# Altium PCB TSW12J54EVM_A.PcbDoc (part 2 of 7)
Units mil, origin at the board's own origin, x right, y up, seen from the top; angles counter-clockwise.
Board outline 6301 x 2680 mil, 10 copper layers (Top Layer - L1, Gnd-Plane - L2, Signals - L3, Gnd-Plane - L4, Pwr Plane - L5, Signals - L6, Gnd-Plane - L7, Signals - L8, Gnd-Plane - L9, Bottom Layer - L10), stack 57.8 mil thick; 650 components, 374 nets, 2074 pads, 1402 vias.
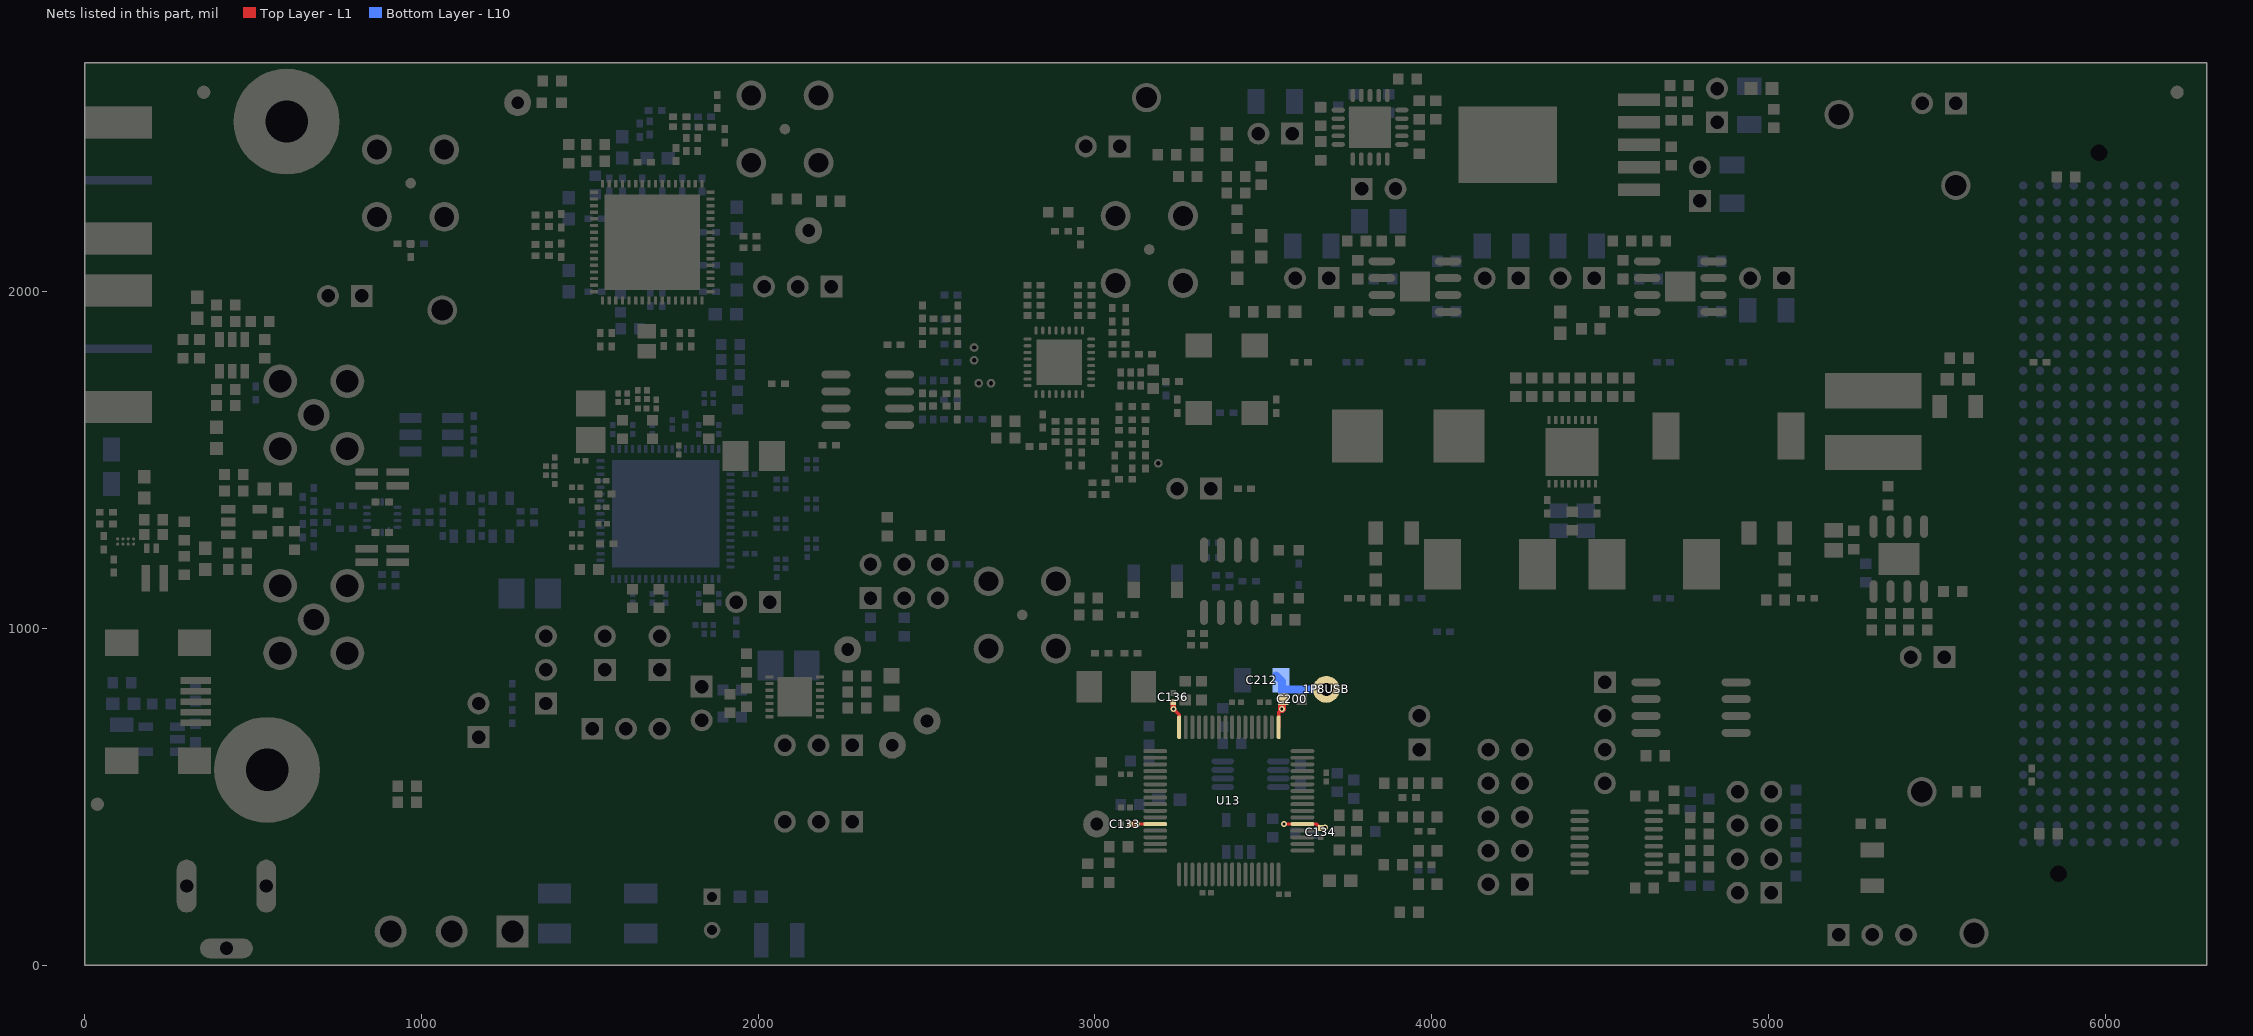
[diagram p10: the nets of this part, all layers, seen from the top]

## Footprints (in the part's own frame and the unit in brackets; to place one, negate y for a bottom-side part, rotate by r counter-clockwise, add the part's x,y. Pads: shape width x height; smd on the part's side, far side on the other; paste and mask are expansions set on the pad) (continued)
0201#2 [mm] "Data from Kemet datasheet CC101_COM dated 7/28/11"
  rect 0.42x0.46 smd mask+0.048: 1(-0.33,0)
  rect 0.46x0.42 smd mask+0.048: 2(0.33,0)
  body extent -0.31,-0.16 0.31,0.16, height 0.26
0306 [mil] "bxl footprint"
  rect 22x67 smd: 1(-20.5,0) 2(20.5,0)
  body extent -17,-33 17,33, height 24
0402L#1 [mm] "0402 from SM-752 data"
  rect 0.6x0.5 smd: 1(-0.5,0) 2(0.5,0)
  body extent -0.55,-0.3 0.55,0.3, height 0.6
0402L#2 [mm] "0402 from SM-752 data"
  rect 0.6x0.5 smd mask+0.071: 1(-0.5,0) 2(0.5,0)
  body extent -0.55,-0.3 0.55,0.3, height 0.6
0402L#3 [mm] "0402 from SM-752 data"
  rect 0.6x0.5 smd: 1(-0.5,0)
  rect 0.6x0.5 smd mask+0.075: 2(0.5,0)
  body extent -0.55,-0.3 0.55,0.3, height 0.6
0402L#4 [mm] "0402 from SM-752 data"
  rect 0.6x0.5 smd: 1(-0.5,0)
  rect 0.6x0.5 smd mask+0.067: 2(0.5,0)
  body extent -0.55,-0.3 0.55,0.3, height 0.6
0402L#5 [mm] "0402 from SM-752 data"
  rect 0.6x0.5 smd mask+0.067: 1(-0.5,0)
  rect 0.6x0.5 smd: 2(0.5,0)
  body extent -0.55,-0.3 0.55,0.3, height 0.6
0402L#6 [mm] "0402 from SM-752 data"
  rect 0.6x0.5 smd mask+0.074: 1(-0.5,0)
  rect 0.6x0.5 smd: 2(0.5,0)
  body extent -0.55,-0.3 0.55,0.3, height 0.6
0402L#7 [mm] "0402 from SM-752 data"
  rect 0.6x0.5 smd: 1(-0.5,0)
  rect 0.6x0.5 smd mask+0.053: 2(0.5,0)
  body extent -0.55,-0.3 0.55,0.3, height 0.6
0402L#8 [mm] "0402 from SM-752 data"
  rect 0.6x0.5 smd mask+0.071: 1(-0.5,0)
  rect 0.6x0.5 smd: 2(0.5,0)
  body extent -0.55,-0.3 0.55,0.3, height 0.6
0402L#9 [mm] "0402 from SM-752 data"
  rect 0.6x0.5 smd: 1(-0.5,0)
  rect 0.6x0.5 smd mask+0.071: 2(0.5,0)
  body extent -0.55,-0.3 0.55,0.3, height 0.6
0402L#10 [mm] "0402 from SM-752 data"
  rect 0.6x0.5 smd mask+0.066: 1(-0.5,0) 2(0.5,0)
  body extent -0.55,-0.3 0.55,0.3, height 0.6
0402L#11 [mm] "0402 from SM-752 data"
  rect 0.6x0.5 smd mask+0.065: 1(-0.5,0)
  rect 0.6x0.5 smd: 2(0.5,0)
  body extent -0.55,-0.3 0.55,0.3, height 0.6
0603 [mm] "0603 from SM-752 data"
  rect 1x0.95 smd: 1(-0.8,0) 2(0.8,0)
  silkscreen extent -1.52,-0.69 1.52,0.69, body extent -0.87,-0.47 0.87,0.47, height 0.85
0603HC [mm] "SMD, 2-Leads, Body 1.8x1.12mm, Lead Spacing 1.28mm"
  rect 0.64x1.02 smd: 1(-0.64,0) 2(0.64,0)
  silkscreen extent -0.18,-0.7 0.18,0.7, body extent -0.9,-0.56 0.9,0.56, height 1.01
0603L#1 [mm] "0603 from SM-752 data"
  rect 0.8x0.85 smd: 1(-0.7,0) 2(0.7,0)
  silkscreen extent -0.07,-0.33 0.07,0.33, body extent -0.87,-0.47 0.87,0.47, height 0.85
0603L#2 [mm] "0603 from SM-752 data"
  rect 0.8x0.85 smd: 1(-0.7,0)
  rect 0.8x0.85 smd mask+0.053: 2(0.7,0)
  silkscreen extent -0.07,-0.33 0.07,0.33, body extent -0.87,-0.47 0.87,0.47, height 0.85
0603L#3 [mm] "0603 from SM-752 data"
  rect 0.8x0.85 smd: 1(-0.7,0)
  rect 0.8x0.85 smd mask+0.064: 2(0.7,0)
  silkscreen extent -0.07,-0.33 0.07,0.33, body extent -0.87,-0.47 0.87,0.47, height 0.85
751-06_N [mm] "SOIC, 8-Leads, Body 4.9x3.9mm, Pitch 1.27mm, IPC Medium Density"
  oval 2.2x0.6 smd: 1(-2.4,1.905) 2(-2.4,0.635) 3(-2.4,-0.635) 4(-2.4,-1.905) 5(2.4,-1.905) 6(2.4,-0.635) 7(2.4,0.635) 8(2.4,1.905)
  silkscreen extent -2.53,-2.5 0.9,2.88, body extent -1.95,-2.45 1.95,2.45, height 1.75
0805L [mm] "0805 from SM-752 data"
  rect 1.1x1.4 smd: 1(-0.75,0) 2(0.75,0)
  body extent -1.1,-0.72 1.1,0.72, height 1.1
1206 [mm] "1206 from SM-752 data"
  rect 1.3x1.85 smd: 1(-1.45,0) 2(1.45,0)
  silkscreen extent -2.4,-1.21 2.4,1.21, body extent -1.7,-0.9 1.7,0.9, height 1.35
1206L [mm] "1206 from SM-752 data"
  rect 1.1x1.75 smd: 1(-1.35,0) 2(1.35,0)
  silkscreen extent -0.4,-0.78 0.4,0.77, body extent -1.7,-0.9 1.7,0.9, height 1.35
1210L [mm] "1210 from SM-752 data"
  rect 1.1x2.6 smd: 1(-1.35,0) 2(1.35,0)
  silkscreen extent -0.4,-1.2 0.4,1.2, body extent -1.7,-1.35 1.7,1.35, height 1.35
3216-18 [mm] "Medium density IPC, based on Kemet T495 dimensions"
  rect 1.8x1.25 smd: 1(-1.3,0) 2(1.3,0)
  silkscreen extent -2.49,-0.54 -2.49,0.54, body extent -1.7,-0.9 1.7,0.9, height 1.8
3528-21 [mm] "Medium Density IPC, based on SM-782 section 8.4"
  rect 1.95x2.25 smd: 1(-1.375,0) 2(1.375,0)
  silkscreen extent -2.66,-1.5 1.9,1.79, body extent -1.85,-1.5 1.85,1.5, height 2.1
AssemblyNote [mil] "Assembly Note"
AssemblyNoteLabel [mil] "Assembly Note for PCB Labels"
CAPPR250W50D630H1120 [mm] "PANASONIC"
  rect 1.25x1.25 hole 0.75: 1(-1.25,0)
  round 1.25 hole 0.75: 2(1.25,0)
  silkscreen extent -3.4,-3.4 3.4,3.4, body extent -3.37,-3.39 3.4,3.39, height 12.21
CDRH6D28 [mm] "Sumida reommended land pattern"
  rect 2.65x7.3 smd: 1(-2.325,0) 2(2.325,0)
  silkscreen extent -4,-4 4,4, body extent -3.5,-3.5 3.5,3.5, height 3
CONN_2510-6002 [mm] "3M 2500 series TS-0770-L December 15, 2011"
  rect 1.65x1.65 hole 1.016 mask+0: 1(-5.08,-1.27)
  round 1.65 hole 1.016 mask+0: 2(-5.08,1.27) 3(-2.54,-1.27) 4(-2.54,1.27) 5(0,-1.27) 6(0,1.27) 7(2.54,-1.27) 8(2.54,1.27) 9(5.08,-1.27) 10(5.08,1.27)
  silkscreen extent -10.01,-4.17 10.01,4.47, body extent -10.01,-4.11 10.01,4.52, height 9.92
CONN_CUI-PJ-202AH [mm] "Conn_DC Jack"
  oval 1.5x4 hole 1 slot 3.5 at 90 deg: 1(0,0) 2(6,0)
  oval 4x1.5 hole 1 slot 3.5 at 0 deg: 3(3,4.7)
  silkscreen extent -0.7,-4.5 13.7,4.5, body extent -0.7,-4.5 13.7,4.9, height 11.02
CONN_LTI_SASF546-P26-X1 [mm]
  round 0.8 smd: 1(0,0)
  round 2.25 hole 1.5 mask+0.051: 2(-2.54,2.54) 3(-2.54,-2.54) 4(2.54,-2.54) 5(2.54,2.54)
  silkscreen extent -3.4,-3.4 3.4,3.4, body extent -3.17,-3.17 3.17,3.17, height 12.53
CONN_SEARAY_ASP-134488-01 [mm]
  round 0.635 hole 1.27 unplated mask+0.572: 401(27.191,0) 402(-27.191,-3.048)
  round 0.64 smd paste+0.125 mask+0.05: A1(24.716,5.715) A2(23.446,5.715) A3(22.176,5.715) A4(20.906,5.715) A5(19.636,5.715) A6(18.366,5.715) A7(17.096,5.715) A8(15.826,5.715) A9(14.556,5.715) A10(13.286,5.715) A11(12.016,5.715) A12(10.746,5.715) A13(9.476,5.715) A14(8.206,5.715) A15(6.936,5.715) A16(5.666,5.715) A17(4.396,5.715) A18(3.126,5.715) A19(1.856,5.715) A20(0.586,5.715) A21(-0.684,5.715) A22(-1.954,5.715) A23(-3.224,5.715) A24(-4.494,5.715) A25(-5.764,5.715) A26(-7.034,5.715) A27(-8.304,5.715) A28(-9.574,5.715) A29(-10.844,5.715) A30(-12.114,5.715) A31(-13.384,5.715) A32(-14.654,5.715) A33(-15.924,5.715) A34(-17.194,5.715) A35(-18.464,5.715) A36(-19.734,5.715) A37(-21.004,5.715) A38(-22.274,5.715) A39(-23.544,5.715) A40(-24.814,5.715) B1(24.716,4.445) B2(23.446,4.445) B3(22.176,4.445) B4(20.906,4.445) B5(19.636,4.445) B6(18.366,4.445) B7(17.096,4.445) B8(15.826,4.445) B9(14.556,4.445) B10(13.286,4.445) B11(12.016,4.445) B12(10.746,4.445) B13(9.476,4.445) B14(8.206,4.445) B15(6.936,4.445) B16(5.666,4.445) B17(4.396,4.445) B18(3.126,4.445) B19(1.856,4.445) B20(0.586,4.445) B21(-0.684,4.445) B22(-1.954,4.445) B23(-3.224,4.445) B24(-4.494,4.445) B25(-5.764,4.445) B26(-7.034,4.445) B27(-8.304,4.445) B28(-9.574,4.445) B29(-10.844,4.445) B30(-12.114,4.445) B31(-13.384,4.445) B32(-14.654,4.445) B33(-15.924,4.445) B34(-17.194,4.445) B35(-18.464,4.445) B36(-19.734,4.445) B37(-21.004,4.445) B38(-22.274,4.445) B39(-23.544,4.445) B40(-24.814,4.445) C1(24.716,3.175) C2(23.446,3.175) C3(22.176,3.175) C4(20.906,3.175) C5(19.636,3.175) C6(18.366,3.175) C7(17.096,3.175) C8(15.826,3.175) C9(14.556,3.175) C10(13.286,3.175) C11(12.016,3.175) C12(10.746,3.175) C13(9.476,3.175) C14(8.206,3.175) C15(6.936,3.175) C16(5.666,3.175) C17(4.396,3.175) C18(3.126,3.175) C19(1.856,3.175) C20(0.586,3.175) C21(-0.684,3.175) C22(-1.954,3.175) C23(-3.224,3.175) C24(-4.494,3.175) C25(-5.764,3.175) C26(-7.034,3.175) C27(-8.304,3.175) C28(-9.574,3.175) C29(-10.844,3.175) C30(-12.114,3.175) C31(-13.384,3.175) C32(-14.654,3.175) C33(-15.924,3.175) C34(-17.194,3.175) C35(-18.464,3.175) C36(-19.734,3.175) C37(-21.004,3.175) C38(-22.274,3.175) C39(-23.544,3.175) C40(-24.814,3.175) D1(24.716,1.905) D2(23.446,1.905) D3(22.176,1.905) D4(20.906,1.905) D5(19.636,1.905) D6(18.366,1.905) D7(17.096,1.905) D8(15.826,1.905) D9(14.556,1.905) D10(13.286,1.905) D11(12.016,1.905) D12(10.746,1.905) D13(9.476,1.905) D14(8.206,1.905) D15(6.936,1.905) D16(5.666,1.905) D17(4.396,1.905) D18(3.126,1.905) D19(1.856,1.905) D20(0.586,1.905) D21(-0.684,1.905) D22(-1.954,1.905) D23(-3.224,1.905) D24(-4.494,1.905) D25(-5.764,1.905) D26(-7.034,1.905) D27(-8.304,1.905) D28(-9.574,1.905) D29(-10.844,1.905) D30(-12.114,1.905) D31(-13.384,1.905) D32(-14.654,1.905) D33(-15.924,1.905) D34(-17.194,1.905) D35(-18.464,1.905) D36(-19.734,1.905) D37(-21.004,1.905) D38(-22.274,1.905) D39(-23.544,1.905) D40(-24.814,1.905) E1(24.716,0.635) E2(23.446,0.635) E3(22.176,0.635) E4(20.906,0.635) E5(19.636,0.635) E6(18.366,0.635) E7(17.096,0.635) E8(15.826,0.635) E9(14.556,0.635) E10(13.286,0.635) E11(12.016,0.635) E12(10.746,0.635) E13(9.476,0.635) E14(8.206,0.635) E15(6.936,0.635) E16(5.666,0.635) E17(4.396,0.635) E18(3.126,0.635) E19(1.856,0.635) E20(0.586,0.635) E21(-0.684,0.635) E22(-1.954,0.635) E23(-3.224,0.635) E24(-4.494,0.635) E25(-5.764,0.635) E26(-7.034,0.635) E27(-8.304,0.635) E28(-9.574,0.635) E29(-10.844,0.635) E30(-12.114,0.635) E31(-13.384,0.635) E32(-14.654,0.635) E33(-15.924,0.635) E34(-17.194,0.635) E35(-18.464,0.635) E36(-19.734,0.635) E37(-21.004,0.635) E38(-22.274,0.635) E39(-23.544,0.635) E40(-24.814,0.635) F1(24.716,-0.635) F2(23.446,-0.635) F3(22.176,-0.635) F4(20.906,-0.635) F5(19.636,-0.635) F6(18.366,-0.635) F7(17.096,-0.635) F8(15.826,-0.635) F9(14.556,-0.635) F10(13.286,-0.635) F11(12.016,-0.635) F12(10.746,-0.635) F13(9.476,-0.635) F14(8.206,-0.635) F15(6.936,-0.635) F16(5.666,-0.635) F17(4.396,-0.635) F18(3.126,-0.635) F19(1.856,-0.635) F20(0.586,-0.635) F21(-0.684,-0.635) F22(-1.954,-0.635) F23(-3.224,-0.635) F24(-4.494,-0.635) F25(-5.764,-0.635) F26(-7.034,-0.635) F27(-8.304,-0.635) F28(-9.574,-0.635) F29(-10.844,-0.635) F30(-12.114,-0.635) F31(-13.384,-0.635) F32(-14.654,-0.635) F33(-15.924,-0.635) F34(-17.194,-0.635) F35(-18.464,-0.635) F36(-19.734,-0.635) F37(-21.004,-0.635) F38(-22.274,-0.635) F39(-23.544,-0.635) F40(-24.814,-0.635) G1(24.716,-1.905) G2(23.446,-1.905) G3(22.176,-1.905) G4(20.906,-1.905) G5(19.636,-1.905) G6(18.366,-1.905) G7(17.096,-1.905) G8(15.826,-1.905) G9(14.556,-1.905) G10(13.286,-1.905) G11(12.016,-1.905) G12(10.746,-1.905) G13(9.476,-1.905) G14(8.206,-1.905) G15(6.936,-1.905) G16(5.666,-1.905) G17(4.396,-1.905) G18(3.126,-1.905) G19(1.856,-1.905) G20(0.586,-1.905) G21(-0.684,-1.905) G22(-1.954,-1.905) G23(-3.224,-1.905) G24(-4.494,-1.905) G25(-5.764,-1.905) G26(-7.034,-1.905) G27(-8.304,-1.905) G28(-9.574,-1.905) G29(-10.844,-1.905) G30(-12.114,-1.905) G31(-13.384,-1.905) G32(-14.654,-1.905) G33(-15.924,-1.905) G34(-17.194,-1.905) G35(-18.464,-1.905) G36(-19.734,-1.905) G37(-21.004,-1.905) G38(-22.274,-1.905) G39(-23.544,-1.905) G40(-24.814,-1.905) H1(24.716,-3.175) H2(23.446,-3.175) H3(22.176,-3.175) H4(20.906,-3.175) H5(19.636,-3.175) H6(18.366,-3.175) H7(17.096,-3.175) H8(15.826,-3.175) H9(14.556,-3.175) H10(13.286,-3.175) H11(12.016,-3.175) H12(10.746,-3.175) H13(9.476,-3.175) H14(8.206,-3.175) H15(6.936,-3.175) H16(5.666,-3.175) H17(4.396,-3.175) H18(3.126,-3.175) H19(1.856,-3.175) H20(0.586,-3.175) H21(-0.684,-3.175) H22(-1.954,-3.175) H23(-3.224,-3.175) H24(-4.494,-3.175) H25(-5.764,-3.175) H26(-7.034,-3.175) H27(-8.304,-3.175) H28(-9.574,-3.175) H29(-10.844,-3.175) H30(-12.114,-3.175) H31(-13.384,-3.175) H32(-14.654,-3.175) H33(-15.924,-3.175) H34(-17.194,-3.175) H35(-18.464,-3.175) H36(-19.734,-3.175) H37(-21.004,-3.175) H38(-22.274,-3.175) H39(-23.544,-3.175) H40(-24.814,-3.175) J1(24.716,-4.445) J2(23.446,-4.445) J3(22.176,-4.445) J4(20.906,-4.445) J5(19.636,-4.445) J6(18.366,-4.445) J7(17.096,-4.445) J8(15.826,-4.445) J9(14.556,-4.445) J10(13.286,-4.445) J11(12.016,-4.445) J12(10.746,-4.445) J13(9.476,-4.445) J14(8.206,-4.445) J15(6.936,-4.445) J16(5.666,-4.445) J17(4.396,-4.445) J18(3.126,-4.445) J19(1.856,-4.445) J20(0.586,-4.445) J21(-0.684,-4.445) J22(-1.954,-4.445) J23(-3.224,-4.445) J24(-4.494,-4.445) J25(-5.764,-4.445) J26(-7.034,-4.445) J27(-8.304,-4.445) J28(-9.574,-4.445) J29(-10.844,-4.445) J30(-12.114,-4.445) J31(-13.384,-4.445) J32(-14.654,-4.445) J33(-15.924,-4.445) J34(-17.194,-4.445) J35(-18.464,-4.445) J36(-19.734,-4.445) J37(-21.004,-4.445) J38(-22.274,-4.445) J39(-23.544,-4.445) J40(-24.814,-4.445) K1(24.716,-5.715) K2(23.446,-5.715) K3(22.176,-5.715) K4(20.906,-5.715) K5(19.636,-5.715) K6(18.366,-5.715) K7(17.096,-5.715) K8(15.826,-5.715) K9(14.556,-5.715) K10(13.286,-5.715) K11(12.016,-5.715) K12(10.746,-5.715) K13(9.476,-5.715) K14(8.206,-5.715) K15(6.936,-5.715) K16(5.666,-5.715) K17(4.396,-5.715) K18(3.126,-5.715) K19(1.856,-5.715) K20(0.586,-5.715) K21(-0.684,-5.715) K22(-1.954,-5.715) K23(-3.224,-5.715) K24(-4.494,-5.715) K25(-5.764,-5.715) K26(-7.034,-5.715) K27(-8.304,-5.715) K28(-9.574,-5.715) K29(-10.844,-5.715) K30(-12.114,-5.715) K31(-13.384,-5.715) K32(-14.654,-5.715) K33(-15.924,-5.715) K34(-17.194,-5.715) K35(-18.464,-5.715) K36(-19.734,-5.715) K37(-21.004,-5.715) K38(-22.274,-5.715) K39(-23.544,-5.715) K40(-24.814,-5.715)
  silkscreen extent -28.49,-8.18 29.69,8.18, body extent -27.89,-7.34 29.49,7.34, height 7.07
CONN_USB-MINI-AB-651-305-142-821 [mm] "WE-USB2-MINI-AB TYPE"
  rect 0.5x2.3 smd: 1(-1.6,2.8) 2(-0.8,2.8) 3(0,2.8) 4(0.8,2.8) 5(1.6,2.8)
  rect 2x2.5 smd: 6(4.45,2.7) 7(4.45,-2.8) 8(-4.45,-2.8) 9(-4.45,2.7)
  silkscreen extent -4.03,-5.6 4,1.1, body extent -4.95,-5.72 4.95,3.68, height 4.12
DBV0005A_N [mm] "SOT23, 5-Leads, Body 2.9x1.6mm, Pitch 0.95mm, Lead Span 2.8mm, IPC Medium Density"
  rect 1.1x0.65 smd: 1(-1.2,0.95) 2(-1.2,0) 3(-1.2,-0.95) 4(1.2,-0.95) 5(1.2,0.95)
  silkscreen extent -1.33,-1.55 0.25,1.95, body extent -0.87,-1.52 0.87,1.53, height 1.45
DBV0006A_N [mm] "SOT23, 6-Leads, Body 2.9x1.6mm, Pitch 0.95mm, Lead Span 2.8mm, IPC Medium Density"
  rect 1.1x0.65 smd: 1(-1.2,0.95) 2(-1.2,0) 3(-1.2,-0.95) 4(1.2,-0.95) 5(1.2,0) 6(1.2,0.95)
  silkscreen extent -1.32,-1.55 0.25,1.95, body extent -1.42,-1.46 1.42,1.46, height 1.11
DDA0008B_L [mm] "SOIC, 8-Leads, Body 4.9x3.9mm, Pitch 1.27mm, Exposed Pad, IPC High Density"
  oval 1.7x0.6 smd: 1(-2.45,1.905) 2(-2.45,0.635) 3(-2.45,-0.635) 4(-2.45,-1.905) 5(2.45,-1.905) 6(2.45,-0.635) 7(2.45,0.635) 8(2.45,1.905)
  rect 2.41x3.1 smd: 9(0,0)
  silkscreen extent -2.57,-2.5 1.2,2.88, body extent -2,-2.5 2,2.5, height 1.68
ESD_Overlay_Small [mil]
  silkscreen extent -62,-48 64,61
FCC_disclaimer [mil]
Fiducial10-30 [mm]
  round 1 smd paste-0.5 mask+1: 1(0,0)
  Keep-Out Layer circle w1.678: c0,0 r0.75
IEC_HotSurface_Small [mil]
  silkscreen extent -107,-93 107,92
IND_TDK_ACM7060 [mm] "TDK Common Mode EMI Filter 7mmx6mm"
  rect 2.5x1.5 smd: 1(-3.25,1.5) 2(-3.25,-1.5) 3(3.25,-1.5) 4(3.25,1.5)
  silkscreen extent -4.8,-3.32 4.75,3.31, body extent -3.6,-3.12 3.6,3.07, height 3.55
Johnson_142-0701-80x [mil] "Johnson Components recommended land pattern"
  rect 25x200 smd: 1(0,0)
  rect 95x200 smd: 2(-172.5,0) 3(172.5,0)
  rect 95x200 smd far side: 4(-172.5,0) 5(172.5,0)
  silkscreen extent -235,-170 235,100, body extent -190,-92 190,480, height 165
Johnson_142-0701-231#1 [mil] "Johnson Components recommended land pattern"
  round 95 hole 62: 1(0,0)
  round 100 hole 67: 2(100,100) 3(100,-100) 4(-100,-100)
  round 100 hole 67 mask+2.5: 5(-100,100)
  silkscreen extent -165,-165 165,165, body extent -156,-156 156,156, height 375
Johnson_142-0701-231#2 [mil] "Johnson Components recommended land pattern"
  round 95 hole 62: 1(0,0)
  round 100 hole 67: 2(100,100) 3(100,-100) 4(-100,-100) 5(-100,100)
  silkscreen extent -165,-165 165,165, body extent -156,-156 156,156, height 375
Keystone5011 [mil] "Keystone Multipurpose loops"
  round 87 hole 63: 1(0,0)
  silkscreen extent -70,-70 70,70, body extent -63,-63 63,62, height 319
Keystone_1902C [mil] "Hex Standoff, 4-40 threaded, nylon"
  round 1 on Mech4: 0(0,0)
  body extent -145,-126 146,126, height 501
LED_LTST-C170 [mm] "LITE-ON"
  rect 1.2x1.2 smd: 1(-1.05,0) 2(1.05,0)
  silkscreen extent -1.6,-1.1 3,1.1, body extent -1.05,-0.67 1.05,0.67, height 1.1
LED_LTST-C190 [mm] "Lite-On"
  rect 0.8x0.8 smd: 1(-0.75,0) 2(0.75,0)
  silkscreen extent -1.1,-0.8 1.8,0.8, body extent -0.85,-0.45 0.85,0.45, height 0.9
LQFP64_N [mm] "Thin QFP, 64-Leads, Body 10x10mm, Pitch 0.5mm, IPC Medium Density"
  oval 1.8x0.3 smd mask+0.049: 1(-5.55,3.75) 2(-5.55,3.25) 3(-5.55,2.75) 4(-5.55,2.25) 5(-5.55,1.75) 6(-5.55,1.25) 7(-5.55,0.75) 8(-5.55,0.25) 9(-5.55,-0.25) 10(-5.55,-0.75) 11(-5.55,-1.25) 12(-5.55,-1.75) 13(-5.55,-2.25) 14(-5.55,-2.75) 15(-5.55,-3.25) 16(-5.55,-3.75) 33(5.55,-3.75) 34(5.55,-3.25) 35(5.55,-2.75) 36(5.55,-2.25) 37(5.55,-1.75) 38(5.55,-1.25) 39(5.55,-0.75) 40(5.55,-0.25) 41(5.55,0.25) 42(5.55,0.75) 43(5.55,1.25) 44(5.55,1.75) 45(5.55,2.25) 46(5.55,2.75) 47(5.55,3.25) 48(5.55,3.75)
  oval 0.3x1.8 smd mask+0.049: 17(-3.75,-5.55) 18(-3.25,-5.55) 19(-2.75,-5.55) 20(-2.25,-5.55) 21(-1.75,-5.55) 22(-1.25,-5.55) 23(-0.75,-5.55) 24(-0.25,-5.55) 25(0.25,-5.55) 26(0.75,-5.55) 27(1.25,-5.55) 28(1.75,-5.55) 29(2.25,-5.55) 30(2.75,-5.55) 31(3.25,-5.55) 32(3.75,-5.55) 49(3.75,5.55) 50(3.25,5.55) 51(2.75,5.55) 52(2.25,5.55) 53(1.75,5.55) 54(1.25,5.55) 55(0.75,5.55) 56(0.25,5.55) 57(-0.25,5.55) 58(-0.75,5.55) 59(-1.25,5.55) 60(-1.75,5.55) 61(-2.25,5.55) 62(-2.75,5.55) 63(-3.25,5.55) 64(-3.75,5.55)
  silkscreen extent -5.67,-4.25 4.25,4.57, body extent -5,-5 5,5, height 1.6
M08A_L [mm] "SOIC, 8-Leads, Body 4.9x3.9mm, Pitch 1.27mm, IPC High Density"
  oval 1.9x0.6 smd: 1(-2.35,1.905) 2(-2.35,0.635) 3(-2.35,-0.635) 4(-2.35,-1.905) 5(2.35,-1.905) 6(2.35,-0.635) 7(2.35,0.635) 8(2.35,1.905)
  silkscreen extent -2.47,-2.5 1,2.88, body extent -2,-2.5 2,2.5, height 1.75
Mini-Circuits-DB1627 [mm] "Mini-Circuits DB1627 Footprint"
  rect 0.76x1.65 smd: 1(-1.27,1.59) 2(0,1.59) 3(1.27,1.59) 4(1.27,-1.59) 5(0,-1.59) 6(-1.27,-1.59)
  silkscreen extent -3.01,-2.03 1.91,2.03, body extent -1.91,-2.03 1.91,2.03, height 4.07
MRA08A_N [mm] "SOIC, 8-Leads, Body 4.9x3.9mm, Pitch 1.27mm, Exposed Pad, IPC Medium Density"
  oval 2x0.6 smd: 1(-2.5,1.905) 2(-2.5,0.635) 3(-2.5,-0.635) 4(-2.5,-1.905) 5(2.5,-1.905) 6(2.5,-0.635) 7(2.5,0.635) 8(2.5,1.905)
  rect 2.29x2.29 smd: 9(0,0)
  silkscreen extent -2.63,-2.5 1.1,2.88, body extent -2,-2.5 2,2.5, height 1.68
MSOP-MS8_N [mm] "TSOP, 8-Leads, Body 3x3mm, Pitch 0.65mm, IPC Medium Density"
  oval 1.7x0.45 smd mask+0.049: 1(-2.1,0.975) 2(-2.1,0.325) 3(-2.1,-0.325) 4(-2.1,-0.975) 5(2.1,-0.975) 6(2.1,-0.325) 7(2.1,0.325) 8(2.1,0.975)
  silkscreen extent -2.22,-1.55 0.85,1.87, body extent -1.6,-1.6 1.6,1.6, height 1.1
MSS1038 [mil]
  rect 80x140 smd: 1(-185,0) 2(185,0)
  silkscreen extent -216,-208 215,208, body extent -203,-201 203,201, height 158
NKD0064A [mm] "QFN, 64-Leads, Body 9x9mm, Pitch 0.5mm"
  rect 0.6x0.25 smd mask+0.051: 1(-4.4,3.75) 2(-4.4,3.25) 3(-4.4,2.75) 4(-4.4,2.25) 5(-4.4,1.75) 6(-4.4,1.25) 7(-4.4,0.75) 8(-4.4,0.25) 9(-4.4,-0.25) 10(-4.4,-0.75) 11(-4.4,-1.25) 12(-4.4,-1.75) 13(-4.4,-2.25) 14(-4.4,-2.75) 15(-4.4,-3.25) 16(-4.4,-3.75) 33(4.4,-3.75) 34(4.4,-3.25) 35(4.4,-2.75) 36(4.4,-2.25) 37(4.4,-1.75) 38(4.4,-1.25) 39(4.4,-0.75) 40(4.4,-0.25) 41(4.4,0.25) 42(4.4,0.75) 43(4.4,1.25) 44(4.4,1.75) 45(4.4,2.25) 46(4.4,2.75) 47(4.4,3.25) 48(4.4,3.75)
  rect 0.25x0.6 smd mask+0.051: 17(-3.75,-4.4) 18(-3.25,-4.4) 19(-2.75,-4.4) 20(-2.25,-4.4) 21(-1.75,-4.4) 22(-1.25,-4.4) 23(-0.75,-4.4) 24(-0.25,-4.4) 25(0.25,-4.4) 26(0.75,-4.4) 27(1.25,-4.4) 28(1.75,-4.4) 29(2.25,-4.4) 30(2.75,-4.4) 31(3.25,-4.4) 32(3.75,-4.4) 49(3.75,4.4) 50(3.25,4.4) 51(2.75,4.4) 52(2.25,4.4) 53(1.75,4.4) 54(1.25,4.4) 55(0.75,4.4) 56(0.25,4.4) 57(-0.25,4.4) 58(-0.75,4.4) 59(-1.25,4.4) 60(-1.75,4.4) 61(-2.25,4.4) 62(-2.75,4.4) 63(-3.25,4.4) 64(-3.75,4.4)
  rect 7.2x7.2 smd paste-3.6 mask+0.051: 65(0,0)
  silkscreen extent -5.52,-4.85 4.85,4.85, body extent -4.55,-4.55 4.55,4.55, height 0.8
"NY PMS 440 0025 PH"#1 [mm] "4-40 nylon screw and mounting hole"
  round 8 / inner round 4.216 / far side round 8 hole 3.2 mask+0.037: 1(0,0)
  body extent -3.3,-3.3 3.3,3.3, height 2.69
"NY PMS 440 0025 PH"#2 [mm] "4-40 nylon screw and mounting hole"
  round 8 / inner round 4.216 / far side round 8 hole 3.2: 1(0,0)
  body extent -3.3,-3.3 3.3,3.3, height 2.69
OSC_CWX [mm] "CONNOR WINFIELD"
  rect 2x1.8 smd: 1(-2.1,2.54) 2(-2.1,-2.54) 3(2.1,-2.54) 4(2.1,2.54)
  silkscreen extent -2.7,-3.7 2.7,4.55, body extent -2.65,-3.65 2.65,3.65, height 1.31
Pb-Free_Overlay_Small [mil]
  silkscreen extent -46,-46 46,46
PBC03SAAN [mm] "Sullins 100mil, 1x3, 230 mil above insulator"
  rect 1.65x1.65 hole 1.016: 1(-2.54,0)
  round 1.65 hole 1.016: 2(0,0) 3(2.54,0)
  silkscreen extent -3.81,-1.27 3.81,1.27, body extent -3.81,-1.27 3.81,1.27, height 8.38
PW0016A_L [mm] "TSOP, 16-Leads, Body 5x4.4mm, Pitch 0.65mm, IPC High Density"
  oval 1.4x0.35 smd: 1(-2.8,2.275) 2(-2.8,1.625) 3(-2.8,0.975) 4(-2.8,0.325) 5(-2.8,-0.325) 6(-2.8,-0.975) 7(-2.8,-1.625) 8(-2.8,-2.275) 9(2.8,-2.275) 10(2.8,-1.625) 11(2.8,-0.975) 12(2.8,-0.325) 13(2.8,0.325) 14(2.8,0.975) 15(2.8,1.625) 16(2.8,2.275)
  silkscreen extent -2.92,-2.55 1.7,3.12, body extent -2.25,-2.55 2.25,2.55, height 1.2
RGW0020A [mm] "QFN, 20-Leads, Body 5x5mm, Pitch 0.65mm, Thermal Pad 3.15x3.15mm, TI Recommended"
  oval 1x0.35 smd paste-0.025 mask+0.07: 1(-2.4,1.3) 2(-2.4,0.65) 3(-2.4,0) 4(-2.4,-0.65) 5(-2.4,-1.3) 11(2.4,-1.3) 12(2.4,-0.65) 13(2.4,0) 14(2.4,0.65) 15(2.4,1.3)
  oval 0.35x1 smd paste-0.025 mask+0.07: 6(-1.3,-2.4) 7(-0.65,-2.4) 8(0,-2.4) 9(0.65,-2.4) 10(1.3,-2.4) 16(1.3,2.4) 17(0.65,2.4) 18(0,2.4) 19(-0.65,2.4) 20(-1.3,2.4)
  rect 3.15x3.15 smd paste-1.575 mask+0.07: 21(0,0)
  silkscreen extent -3.5,-2.73 2.73,2.73, body extent -2.58,-2.57 2.57,2.58, height 1
RHB0032E [mm] "QFN, 32-Leads, Body 5x5mm, Pitch 0.5mm, Thermal Pad 3.45x3.45mm, TI Recommended"
  oval 0.6x0.24 smd mask+0.07: 1(-2.4,1.75) 2(-2.4,1.25) 3(-2.4,0.75) 4(-2.4,0.25) 5(-2.4,-0.25) 6(-2.4,-0.75) 7(-2.4,-1.25) 8(-2.4,-1.75) 17(2.4,-1.75) 18(2.4,-1.25) 19(2.4,-0.75) 20(2.4,-0.25) 21(2.4,0.25) 22(2.4,0.75) 23(2.4,1.25) 24(2.4,1.75)
  oval 0.24x0.6 smd mask+0.07: 9(-1.75,-2.4) 10(-1.25,-2.4) 11(-0.75,-2.4) 12(-0.25,-2.4) 13(0.25,-2.4) 14(0.75,-2.4) 15(1.25,-2.4) 16(1.75,-2.4) 25(1.75,2.4) 26(1.25,2.4) 27(0.75,2.4) 28(0.25,2.4) 29(-0.25,2.4) 30(-0.75,2.4) 31(-1.25,2.4) 32(-1.75,2.4)
  rect 3.45x3.45 smd paste-1.725 mask+0.07: 33(0,0)
  silkscreen extent -2.72,2.29 -2.29,2.73, body extent -2.57,-2.57 2.58,2.58, height 1.01
RLY0068A [mm] "QFN, 68-Leads, Body 10x10mm, Pitch 0.5mm"
  rect 0.6x0.25 smd mask+0.051: 1(-4.9,4) 2(-4.9,3.5) 3(-4.9,3) 4(-4.9,2.5) 5(-4.9,2) 6(-4.9,1.5) 7(-4.9,1) 8(-4.9,0.5) 9(-4.9,0) 10(-4.9,-0.5) 11(-4.9,-1) 12(-4.9,-1.5) 13(-4.9,-2) 14(-4.9,-2.5) 15(-4.9,-3) 16(-4.9,-3.5) 17(-4.9,-4) 35(4.9,-4) 36(4.9,-3.5) 37(4.9,-3) 38(4.9,-2.5) 39(4.9,-2) 40(4.9,-1.5) 41(4.9,-1) 42(4.9,-0.5) 43(4.9,0) 44(4.9,0.5) 45(4.9,1) 46(4.9,1.5) 47(4.9,2) 48(4.9,2.5) 49(4.9,3) 50(4.9,3.5) 51(4.9,4)
  rect 0.25x0.6 smd mask+0.051: 18(-4,-4.9) 19(-3.5,-4.9) 20(-3,-4.9) 21(-2.5,-4.9) 22(-2,-4.9) 23(-1.5,-4.9) 24(-1,-4.9) 25(-0.5,-4.9) 26(0,-4.9) 27(0.5,-4.9) 28(1,-4.9) 29(1.5,-4.9) 30(2,-4.9) 31(2.5,-4.9) 32(3,-4.9) 33(3.5,-4.9) 34(4,-4.9) 52(4,4.9) 53(3.5,4.9) 54(3,4.9) 55(2.5,4.9) 56(2,4.9) 57(1.5,4.9) 58(1,4.9) 59(0.5,4.9) 60(0,4.9) 61(-0.5,4.9) 62(-1,4.9) 63(-1.5,4.9) 64(-2,4.9) 65(-2.5,4.9) 66(-3,4.9) 67(-3.5,4.9) 68(-4,4.9)
  rect 8.1x8.1 smd paste-4.05 mask+0.051: 69(0,0)
  silkscreen extent -5.87,-5.2 5.2,5.2, body extent -5.05,-5.05 5.05,5.05, height 1.01
RMS0014A [mm] "QFN, Body 2.6x2.6mm, Pitch 0.5mm"
  oval 0.7x0.25 smd: 1(-1.1,0.5)
  oval 0.6x0.25 smd: 2(-1.15,0) 3(-1.15,-0.5) 8(1.15,-0.5) 9(1.15,0) 10(1.15,0.5)
  oval 0.25x0.6 smd: 4(-0.75,-1.15) 5(-0.25,-1.15) 6(0.25,-1.15) 7(0.75,-1.15) 11(0.75,1.15) 12(0.25,1.15) 13(-0.25,1.15) 14(-0.75,1.15)
  silkscreen extent -1.4,-1.4 1.4,1.4, body extent -1.3,-1.3 1.3,1.3, height 0.61
SDA14B [mm] "SON, 14-Leads, Body 4x4mm, Pitch 0.5mm, NSC Recommended"
  rect 0.6x0.25 smd paste-0.125 mask+0.051: 1(-1.9,1.5) 2(-1.9,1) 3(-1.9,0.5) 4(-1.9,0) 5(-1.9,-0.5) 6(-1.9,-1) 7(-1.9,-1.5) 8(1.9,-1.5) 9(1.9,-1) 10(1.9,-0.5) 11(1.9,0) 12(1.9,0.5) 13(1.9,1) 14(1.9,1.5)
  rect 2.6x3 smd paste-1.3 mask+0.051: 15(0,0)
  silkscreen extent -2.82,-2.2 2.35,2.87, body extent -2.05,-2.05 2.05,2.05, height 0.8
SDA16A [mm] "SON, 16-Leads, Body 5x5mm, Pitch 0.5mm, NSC Recommended"
  rect 0.6x0.25 smd paste-0.125 mask+0.051: 1(-2.4,1.75) 2(-2.4,1.25) 3(-2.4,0.75) 4(-2.4,0.25) 5(-2.4,-0.25) 6(-2.4,-0.75) 7(-2.4,-1.25) 8(-2.4,-1.75) 9(2.4,-1.75) 10(2.4,-1.25) 11(2.4,-0.75) 12(2.4,-0.25) 13(2.4,0.25) 14(2.4,0.75) 15(2.4,1.25) 16(2.4,1.75)
  rect 3.6x4 smd paste-1.8 mask+0.051: 17(0,0)
  silkscreen extent -2.85,-2.7 2.85,3.53, body extent -2.55,-2.55 2.55,2.55, height 0.8
SMC [mil] "Molded Diode, 2-Leads, Body 6.9x5.8mm, IPC Medium Density, based on OnSemi component dimensions and land patterns"
  rect 110x150 smd: 1(-140.49,0) 2(140.49,0)
  silkscreen extent -221,-124 189,124, body extent -156,-116 156,116, height 91
SNT-100-BK-G [mil] "Samtec STEP model"
  round 1 on Mech3: 0(0,0)
  body extent -100,-50 100,50, height 344
SOD882 [mm] "NXP Semiconductor"
  rect 0.4x0.7 smd paste-0.05: 1(-0.35,0) 2(0.35,0)
  silkscreen extent -0.95,-0.35 -0.72,0.35, body extent -0.51,-0.31 0.51,0.31, height 0.51
SOD-123 [mm] "On Semi recommended land pattern"
  rect 0.915x1.22 smd: 1(-1.637,0) 2(1.637,0)
  silkscreen extent -2.74,-1.17 2.03,1.17, body extent -1.93,-0.9 1.93,0.9, height 1.35
SOIJ-SM8_N [mm] "SOP, 8-Leads, Body 5.2x5.2mm, Pitch 1.27mm, IPC Medium Density"
  oval 2.2x0.6 smd: 1(-3.4,1.905) 2(-3.4,0.635) 3(-3.4,-0.635) 4(-3.4,-1.905) 5(3.4,-1.905) 6(3.4,-0.635) 7(3.4,0.635) 8(3.4,1.905)
  silkscreen extent -3.52,-2.75 1.9,2.88, body extent -2.73,-2.75 2.73,2.75, height 2.04
SOP-5_.95MM_(DBV) [mil]
  rect 42x25 smd: 1(-48.94,37.39) 2(-48.94,0) 3(-48.94,-37.39) 4(45.94,-37.39) 5(45.94,37.39)
  silkscreen extent -109,25 -84,50
"SW_ L101011MS02Q" [mm] "SWITCH SLIDE sPST 4A PCB"
  rect 2.416x2.416 hole 1.65: 1(2.855,4.6)
  round 2.416 hole 1.65: 2(2.855,0) 3(2.855,-4.6)
  silkscreen extent -5.4,-9.55 5.4,9.55, body extent -5.39,-9.55 5.39,9.55, height 14.18
TESTPOINT#1 [mil]
  round 80 hole 37.99: 1(0,0)
TESTPOINT#2 [mil]
  round 25.98 hole 12.99: 1(0,0)
TESTPOINT#3 [mil]
  round 25.98 hole 12.99: 1(0,23.68)
TI_Symbol_Overlay_Small [mil]
  silkscreen extent -90,-88 91,88
TJ5A_N [mm] "D2-PAK, 6-Leads, Body 9.9x10.2mm, Pitch 1.7mm, Lead Span 14mm, IPC Medium Density"
  rect 3.2x0.95 smd: 1(-6,3.4) 2(-6,1.7) 3(-6,0) 4(-6,-1.7) 5(-6,-3.4)
  rect 7.4x5.75 smd: 6(3.9,0)
  silkscreen extent -6.12,-5.2 -0.2,5.2, body extent -1.95,-5.2 8.15,5.2, height 2.1
TSW-102-07-G-S [mm] "Samtec 100mil, 1x2, 230 mil above insulator"
  rect 1.65x1.65 hole 1.016 mask+0: 1(-1.27,0)
  round 1.65 hole 1.016 mask+0: 2(1.27,0)
  silkscreen extent -3.56,-1.27 2.54,1.27, body extent -2.54,-1.27 2.54,1.27, height 8.38
TSW-103-07-G-D [mm] "Samtec 100mil, 2x3, 230 mil above insulator"
  rect 1.65x1.65 hole 1.016 mask+0: 1(-2.54,-1.27)
  round 1.65 hole 1.016 mask+0: 2(-2.54,1.27) 3(0,-1.27) 4(0,1.27) 5(2.54,-1.27) 6(2.54,1.27)
  silkscreen extent -4.83,-2.54 3.81,2.54, body extent -3.81,-2.54 3.81,2.54, height 8.38
TSW-103-07-G-S [mm] "Samtec 100mil, 1x3, 230 mil above insulator"
  rect 1.65x1.65 hole 1.016 mask+0: 1(-2.54,0)
  round 1.65 hole 1.016 mask+0: 2(0,0) 3(2.54,0)
  silkscreen extent -4.84,-1.27 3.81,1.27, body extent -3.81,-1.27 3.81,1.27, height 8.38
TSW-104-07-G-D [mm] "Samtec 100mil, 2x4, 230 mil above insulator"
  rect 1.65x1.65 hole 1.016 mask+0: 1(-3.81,-1.27)
  round 1.65 hole 1.016 mask+0: 2(-3.81,1.27) 3(-1.27,-1.27) 4(-1.27,1.27) 5(1.27,-1.27) 6(1.27,1.27) 7(3.81,-1.27) 8(3.81,1.27)
  silkscreen extent -6.1,-2.54 5.08,2.54, body extent -5.08,-2.54 5.08,2.54, height 8.38
TSW-104-07-G-S [mm] "Samtec 100mil, 1x4, 230 mil above insulator"
  rect 1.65x1.65 hole 1.016 mask+0: 1(-3.81,0)
  round 1.65 hole 1.016 mask+0: 2(-1.27,0) 3(1.27,0) 4(3.81,0)
  silkscreen extent -6.1,-1.27 5.08,1.27, body extent -5.08,-1.27 5.08,1.27, height 8.38
VLS2012 [mm] "TDK"
  rect 0.65x2 smd: 1(-0.675,0) 2(0.675,0)
  silkscreen extent -0.15,-1.15 0.15,1.15, body extent -1.05,-1.05 1.05,1.05, height 1.2
WE-HC6 [mm] "Wurth Electronik recommended land pattern"
  rect 3.85x4 smd: 1(-3.825,0) 2(3.825,0)
  silkscreen extent -6.2,-6.2 6.2,6.2, body extent -5.77,-5.37 5.75,5.35, height 5
XTAL_ABM3 [mm] "Abracon recommended land pattern 12.28.10"
  rect 1.9x2.4 smd: 1(-2.05,0) 2(2.05,0)
  silkscreen extent -2.67,-1.78 2.67,1.78, body extent -2.6,-1.7 2.6,1.7, height 1.3
YFX0008ADAC [mm] "WCSP, 8-Leads, Body 1.645x0.855mm, Pitch 0.4mm"
  round 0.23 smd paste-0.13 mask+0.038: A1(-0.2,0.6) A2(0.2,0.6) B1(-0.2,0.2) B2(0.2,0.2) C1(-0.2,-0.2) C2(0.2,-0.2) D1(-0.2,-0.6) D2(0.2,-0.6)
  silkscreen extent -0.7,0.81 -0.53,0.99, body extent -0.45,-0.84 0.45,0.84, height 0.68

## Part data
1P8USB 3P3USB LD1 LD2 LO2_N LO2_P LO3_N LO3_P TCRIT1 TCRIT2 TCRIT3 Vtune: "TEST POINT.  No entry in BOM."
1V2ADC_INT 1V2ADC_LDO 1V9ADC 1V9INT EXT_Vcmo J2 J3 "KC705 JTAG" "LMH PD" LMK_INT LMK_LDO LMX_INT LMX_LDO PG_RX1 Tdiode VA12 VA19 Vbg VD12: "Header, TH, 100mil, 2x1, Gold plated, 230 mil above insulator"
3P3RX GND GND1 GND2 GND3 VADJ_RX: "Test Point, TH, Multipurpose, Black"
5VDC: "Connector, DC Jack 2.1X5.5 mm, TH"
12V LD Status1 Status2 USB_PWR: "LED, Green, SMD"
C2 C8 C11 C94 C95 C96 C215 C216 C217 C218 C219 C220 C221 C222 C223 C224 C225 C226 C227 C261: "CAP, CERM, 0.1uF, 10V, +/-10%, X7R, 0402"
C7 C9 C10 C12 C13 C14 C15 C17 C20 C21 C22 C23 C26 C28 C29 C31 C41 C42 C43 C44 C45 C46 C47 C51 C52 C53 C54 C55 C56 C57 C58 C62 C63 C64 C65 C66 C67 C68 C69 C70 C71 C118 C119 C131 C132 C133 C134 C136 C140 C142 C214: library part Capacitor, "CAP, CERM, 0.1uF, 6.3V, X5R, 10%, 0201"
C16: "CAP, CERM, 4.7uF, 6.3V, +/-20%, X5R, 0402"
C18 C19 C73 C85 C86 C87 C88 C89 C103 C104 C105 C106 C107 C109 C110 C111 C112 C113 C114 C120 C121 C123 C124 C206 C207 C208 C209 C231 C235 C250 C251 C258 C259 C260 C273 C274: "CAP, CERM, 0.1uF, 10V, +/-10%, X5R, 0402"
C24 C115 C210: "CAP, CERM, 0.1uF, 16V, +/-5%, X7R, 0603"
C25 C34 C38: "CAP, CERM, 100pF, 50V, +/-5%, C0G/NP0, 0603"
C27 C48 C59 C72: "CAP, TANT, 10uF, 10V, +/-20%, 2.5 ohm, 3528-21 SMD"
C30 C36: "CAP, CERM, 0.22uF, 6.3V, +/-20%, X5R, 0201"
C32 C33 C35 C37 C90 C91 C92 C93 C262 C263: "CAP, CERM, 4700pF, 10V, +/-10%, X5R, 0201"
C39 C40 C49 C50 C60 C61 C125 C143 C205: "CAP, CERM, 1uF, 10V, +/-10%, X5R, 0603"
C74: "CAP, CERM, 100pF, 25V, +/-5%, C0G/NP0, 0402"
C75 C76 C83 C84 C245: "CAP, CERM, 47pF, 50V, +/-5%, C0G/NP0, 0402"
C77 C79 C239 C242 C253 C256 C272: "CAP, CERM, 0.01uF, 25V, +/-10%, X7R, 0402"
C78 C80 C254 C257: "CAP, CERM, 27pF, 50V, +/-5%, C0G/NP0, 0402"
C81 C82 C232 C236 C240 C243 C252 C255: "CAP, CERM, 1uF, 6.3V, +/-20%, X5R, 0402"
C102: "CAP, CERM, 0.01uF, 16V, +/-10%, X7R, 0402"
C108 C155 C201 C211: "CAP, CERM, 1uF, 16V, +/-10%, X5R, 0603"
C116 C126 C129 C130 C144 C147 C148 C151 C153 C159 C164 C167 C176 C177 C185 C189 C191 C198 C199 C213 C277 C281 C283 C288 C290: "CAP, CERM, 0.1uF, 25V, +/-5%, X7R, 0603"
C117 C149: "CAP, CERM, 330pF, 50V, +/-5%, C0G/NP0, 0603"
C122: "CAP, CERM, 10uF, 10V, +/-10%, X5R, 0805"
C127 C160: "CAP, CERM, 4.7uF, 10V, +/-10%, X5R, 0603"
C128 C161 C278: "CAP, CERM, 0.01uF, 100V, +/-20%, X7R, 0603"
C135 C137: "CAP, CERM, 18pF, 50V, +/-5%, C0G/NP0, 0402"
C138 C212: "CAP, CERM, 100uF, 6.3V, +/-20%, X5R, 1206"
C139 C141 C150 C152 C158 C163 C165 C166 C171 C172 C186 C188 C190 C195 C196 C197 C200 C202 C203 C204 C276 C280 C282 C289: "CAP, CERM, 10uF, 10V, +/-10%, C0G/NP0, 0603"
C145 C146 C173 C184: "CAP, CERM, 10uF, 16V, +/-10%, X5R, 0805"
C154: "CAP, CERM, 10pF, 50V, +/-5%, C0G/NP0, 0603"
C156 C157: "CAP, CERM, 47uF, 6.3V, +/-20%, X5R, 1206"
C162: "CAP, CERM, 3300pF, 25V, +/-10%, X7R, 0603"
C168: "CAP, CERM, 0.22uF, 16V, +/-10%, X7R, 0603"
C169 C170: "CAP, CERM, 0.1uF, 6.3V, +/-10%, X5R, 0402"
C174 C175: "CAP, CERM, 0.027uF, 16V, +/-10%, X7R, 0603"
C178 C179: "CAP, CERM, 0.039uF, 25V, +/-10%, X7R, 0603"
C180 C181 C182 C183: "CAP, CERM, 22uF, 10V, +/-20%, X5R, 1206"
C187: "CAP, CERM, 560pF, 50V, +/-5%, C0G/NP0, 0603"
C192: "CAP, CERM, 4700pF, 16V, +/-10%, X7R, 0603"
C193: "CAP, AL, 100uF, 25V, +/-20%, TH"
C194: "CAP, CERM, 10uF, 25V, +/-10%, X6S, 1210"
C228 C229: library part GRM155R71A104KA01D, "CAP CER 0.5PF 50V NP0 0402"
C230 C234 LF2: "CAP, CERM, 47pF, 50V, +/-5%, C0G/NP0, 0603"
C233 C237 C238 C241 C246 C248: "CAP, CERM, 4.7pF, 50V, +/-5%, C0G/NP0, 0402"
C244: "CAP, CERM, 560pF, 50V, +/-5%, C0G/NP0, 0402"
C247: "CAP, CERM, 2.2pF, 50V, +/-5%, C0G/NP0, 0402"
C249: "CAP, CERM, 22pF, 50V, +/-5%, C0G/NP0, 0402"
C264 C265 C270 C271: "CAP, CERM, 0.01uF, 25V, +/-20%, X7R, 0306"
C266 C267 C268 C269: "CAP, CERM, 2200pF, 50V, +/-20%, X7R, 0306"
C275: "CAP, TA, 10uF, 10V, +/-10%, 0.9 ohm, SMD"
C279: "CAP, CERM, 15 pF, 50 V, +/- 5%, C0G/NP0, 0603"
C284 C285: "CAP, CERM, 22 µF, 6.3 V, +/- 20%, X5R, 0603"
C286: "CAP, CERM, 10 pF, 50 V, +/- 5%, C0G/NP0, 0402"
C287: "CAP, CERM, 2.2 µF, 10 V, +/- 10%, X5R, 0603"
C291 C292: "CAP, CERM, 1 pF, 50 V, +/- 5%, C0G/NP0, 0402"
C293 C294: "CAP, CERM, 2.7 pF, 50 V, +/- 5%, C0G/NP0, 0402"
C295 C296: library part Capacitor, "CAP, CERM, xxxF, xxV, [TempCo], xx%, [PackageReference]"
D1: "Diode, Schottky, 30 V, 0.5 A, SOD882"
D2 D4: "Diode, Ultrafast, 100V, 0.15A, SOD-123"
D11 D12: "Diode, Schottky, 40V, 5A, SMC"
DEVCLK EXT_VCO LMKCLK OSCin: "Connector, SMA,Vertical, Thru hole w/SMT center pin"
EXT5V_FMC12V: "Header, TH, 100mil, 1x3, Gold plated, 230 mil above insulator"
FID1 FID2 FID3: "Fiducial mark.  There is nothing to buy or mount."
FMC_RX1: "Connector, Receptacle, 400-Pos (40x10), 50x50-mil Pitch, SMT"
FTDI_3P3V OR RSV "Ts ADD1" Vcmo: "Header, TH, 100mil, 3x1, Gold plated, 230 mil above insulator"
H3 H4: library part 1902C, "Standoff, Round, 3/16\"  x 1-3/16\"L #4-40 Aluminum"
H5 H6: "Machine Screw, Round, #4-40 x 1/4, Nylon, Philips panhead"
J1: "Header, TH, 100mil, 4x1, Gold plated, 230 mil above insulator"
L1 L27 L28 L29 L30 L31 L32 L33 L34: "0.25A Ferrite Bead, 1000 ohm @ 100MHz, SMD"
L2 L3 L4 L5 L19 L21 L22 L23: "1.5A Ferrite Bead, 330 ohm @ 100MHz, SMD"
L6 L9 L10 L13 L15 L16 L17 L18 L26: "6A Ferrite Bead, 26 ohm @ 100MHz, SMD"
L7 L14 L20 L24 L25 L35 L36 L42 L43 L44: "3A Ferrite Bead, 120 ohm @ 100MHz, SMD"
L8: "Inductor, Shielded Drum Core, Ferrite, 3uH, 3A, 0.024 ohm, SMD"
L11: "Inductor, Shielded Drum Core, Ferrite, 7uH, 4.35A, 0.03 ohm, SMD"
L12: "Inductor, Shielded Drum Core, Superflux, 5.5uH, 10A, 0.0112 ohm, SMD"
L37: "Inductor, Shielded, Ferrite, 6.8 µH, 0.57 A, 0.498 ohm, SMD"
L38 L39: "Inductor, Wirewound, Ceramic, 6.8 nH, 2.1 A, 0.054 ohm, SMD"
L40 L41: "Inductor, Wirewound, Ceramic, 3.6 nH, 2.3 A, 0.048 ohm, SMD"
LF1: "CAP, CERM, 3900pF, 25V, +/-5%, C0G/NP0, 0603"
LF3: "RES, 619 ohm, 1%, 0.1W, 0603"
LF7: "Coupled inductor, 5A, 0.01 ohm, SMD"
Logo1: library part ESD_Susceptible, "ESD Susceptible Symbol"
Logo2: library part TI_Logo, "Texas Instrument Corporate Signature"
Logo3: library part Pb-Free
Logo4: library part FCC_disclaimer, "FCC_disclaimer"
LOGO5: library part IEC_HotSurface, "IEC 61010-1 Hot Surface Warning"
NCO: "Header, TH, 100mil, 3x2, Gold plated, 230 mil above insulator"
OR_T0 OR_T1: "LED, Orange, SMD"
R1: "RES, 8.06k ohm, 1%, 0.063W, 0402"
R2 R10: "RES, 1.2k ohm, 5%, 0.063W, 0402"
R3 R11 R150: "RES, 1.0Meg ohm, 5%, 0.063W, 0402"
R4 R5 R6 R14 R15 R16 R105 R106 R107 R123 R130 R131: "RES, 10.0k ohm, 1%, 0.1W, 0603"
R7 R8 R9 R18 R19 R20 R21 R22 R23: "RES, 0 ohm, 5%, 0.05W, 0201"
R12: "RES, 1.33k ohm, 1%, 0.063W, 0402"
R13: "RES, 3.30k ohm, 0.1%, 0.1W, 0603"
R17: "RES, 750 ohm, 5%, 0.1W, 0603"
R24 R144: "RES, 10.0k ohm, 1%, 0.063W, 0402"
R25 R26 R29 R36 R38 R43 R44 R48 R59 R60 R61 R62 R63 R64 R145 R146 R147 R148 R149 R160 R161 R178 R179 R180: "RES, 0 ohm, 5%, 0.063W, 0402"
R27 R28 R34 R35 R181: "RES, 100 ohm, 1%, 0.063W, 0402"
R30 R153: "RES, 49.9 ohm, 1%, 0.063W, 0402"
R31 R32 R122: "RES, 1.3k ohm, 5%, 0.1W, 0603"
R33 R37: "RES, 3.3k ohm, 5%, 0.063W, 0402"
R39 R71 R80 R134: "RES, 1.0k ohm, 5%, 0.1W, 0603"
R40 R42 R73 R75 R83 R84 R92 R95: "RES, 0.002 ohm, 1%, 1W, 1206"
R41 R74: "RES, 10.7k ohm, 1%, 0.1W, 0603"
R45 R56 R112: "RES, 270 ohm, 5%, 0.1W, 0603"
R47: "RES, 2.32k ohm, 1%, 0.1W, 0603"
R49 R77: "RES, 4.64k ohm, 1%, 0.1W, 0603"
R50: library part Resistor, "RES, xxx ohm, x%, xW, [PackageReference]"
R51 R165: "RES, 51 ohm, 5%, 0.063W, 0402"
R52 R53: "RES, 10 ohm, 5%, 0.1W, 0603"
R54 R55 R57 R58 R65 R68 R69 R109 R110 R111 R113 R114 R115 R117 R118 R119 R120 R121 R124 R125 R126 R127: "RES, 100 ohm, 5%, 0.1W, 0603"
R66 R93: "RES, 1.00k ohm, 1%, 0.1W, 0603"
R67: "RES, 12.0k ohm, 1%, 0.1W, 0603"
R70: "RES, 10k ohm, 5%, 0.1W, 0603"
R72 R177: "RES, 95.3 k, 1%, 0.1 W, 0603"
R76: "RES, 22.1k ohm, 1%, 0.1W, 0603"
R78: "RES, 10.0 ohm, 1%, 0.1W, 0603"
R79: "RES, 732 ohm, 1%, 0.1W, 0603"
R81: "RES, 16.2k ohm, 1%, 0.1W, 0603"
R82: "RES, 7.87k ohm, 1%, 0.1W, 0603"
R85: "RES, 2.49k ohm, 1%, 0.1W, 0603"
R86 R87: "RES, 5.90k ohm, 1%, 0.1W, 0603"
R88 RR6: "RES, 4.99k ohm, 1%, 0.1W, 0603"
R89: "RES, 2.80k ohm, 1%, 0.1W, 0603"
R90: "RES, 402 ohm, 1%, 0.1W, 0603"
R91: "RES, 4.99k ohm, 1%, 0.063W, 0402"
R94: "RES, 1.0k ohm, 5%, 0.25W, 1206"
R96: "RES, 357 ohm, 1%, 0.1W, 0603"
R97 R98 R101 R102: "RES, 12.4k ohm, 1%, 0.1W, 0603"
R99 R100 R103 R132 R142 R143 R151 R152 RR7: "RES, 0 ohm, 5%, 0.1W, 0603"
R104 R116 R128 R129: "RES, 24k ohm, 5%, 0.063W, 0402"
R108: "RES, 2.2k ohm, 5%, 0.1W, 0603"
R133 R170 R173: "RES, 1.00k ohm, 1%, 0.063W, 0402"
R135: "RES, 2.10k ohm, 1%, 0.1W, 0603"
R136 R137 R138: "RES, 4.7k ohm, 5%, 0.1W, 0603"
R139 R140 R141: "RES, 2.0k ohm, 5%, 0.1W, 0603"
R154: "RES, 261, 1%, 0.063 W, 0402"
R156 R157: "RES, 127 ohm, 1%, 0.063W, 0402"
R158 R159: "RES, 82.5 ohm, 1%, 0.063W, 0402"
R162: "RES, 107 ohm, 1%, 0.063W, 0402"
R163 R164: "RES, 2.2k ohm, 5%, 0.063W, 0402"
R166 R167: "RES, 560, 5%, 0.063 W, 0402"
R168 Ri+: "RES, 365, 1%, 0.063 W, 0402"
R169 Ri-: "RES, 22.6, 1%, 0.063 W, 0402"
R171: "RES, 62.0 k, 1%, 0.1 W, 0603"
R172: "RES, 30.1 k, 1%, 0.1 W, 0603"
R174: "RES, 274 k, 1%, 0.063 W, 0402"
R175: "RES, 100 k, 1%, 0.063 W, 0402"
R176: "RES, 5.23 k, 1%, 0.1 W, 0603"
R182 R183: "RES, 2.00 k, 1%, 0.063 W, 0402"
Rf+ Rf-: "RES, 127, 1%, 0.063 W, 0402"
Ro+ Ro-: "RES, 40.2 ohm, 1%, 0.063W, 0402"
S1: "SWITCH SLIDE SPST 4A PCB, TH"
SH-1V2ADC_INT_1_2 SH-1V2ADC_LDO_1_2 SH-1V9ADC_1_2 SH-1V9INT_1_2 SH-5V_12V_1_2 SH-FTDI_3P3V_1_2 SH-J2_1_2 SH-LMK_INT_1_2 SH-LMK_LDO_1_2 SH-LMX_INT_1_2 SH-LMX_LDO_1_2 SH-RSV_1_2 "SH-Ts ADD1_1_2" Vcmo_2_3: "Shunt, 100mil, Gold plated, Black"
SPI: "Header, TH, 100mil, 4x2, Gold plated, 230 mil above insulator"
T2: "Transformer, RF, 50 ohm, 10 to 4000 MHz, SMT"
TEMP: "LED, Red, SMD"
TMST+ TMST-: "Connector, SMT, End launch SMA 50 ohm"
U1: library part LMC6762AIMX, "Dual Micro-Power Rail-to-Rail Input CMOS Comparator with Push-Pull Output, 8-pin Narrow SOIC"
U2: library part ADC12X3500RFLQNOPB, "ADC12J4000RLY Ultra-Wideband RF Sampling Subsystem, RLY0068A"
U3: "Dual Remote Diode and Local Temperature Sensor with SMBus Interface and TruTherm Technology, 14-pin LLP, Pb-Free"
U4: "Integer-N/Fractional-N PLL with Integrated VCO, RHB0032E"
U5 U8: "Micropower 800mA Low Noise \"Ceramic Stable\" Adjustable Voltage Regulator for 1V to 5V Applications, 8-pin PSOP, Pb-Free"
U6: "Low-Noise Clock Jitter Cleaner with Dual Loop PLLs, NKD0064A"
U7: "3-A OUTPUT SINGLE SYNCRONOUS STEP DOWN SWITCHER WITH INTEGRATED FET(SWIFT), DDA0008B"
U9: "Dual 2A, 500kHz Wide Input Range Buck Regulator, 16-pin LLP, Pb-Free"
U10: "3.0A Low Dropout Linear Regulator with Programmable Soft-Start, RGW0020A"
U11: "3A Fast-Transient Response Adjustable Low-Dropout Linear Voltage Regulator, 5-pin TO-263 Thin, Pb-Free"
U12: "4-BIT DUAL-SUPPLY BUS TRANSCEIVER WITH CONFIGURABLE VOLTAGE TRANSLATION AND 3-STATE OUTPUTS, PW0016A"
U13: "Quad High Speed USB to Multipurpose UART/MPSSE IC"
U14: "300-mA, Low-IQ, Low-Dropout Regulator, DBV0005A"
U15: "1K, 64x16-bit, 2.5V Microwire Serial EEPROM, 8-Pin MSOP, Industrial Temperature"
U16: "64Kbit, 400kHz, 4.5V, I2C Serial EEPROM, 8-Pin SOIC 208mil, Commercial Temperature, Tape and Reel"
U17: "Divide-by-2 Divider"
U18: "IC, Single Bus Buffer Gate With 3-States Output"
U19: library part LMH5401RMS, "8GHz Ultra Wideband Fully Differential Amplifier, RMS0014A"
U20: "Single Output High PSRR LDO, 200 mA, Adjustable 1.22 to 5.5 V Output, 2.7 to 5.5 V Input, 6-pin SOT-23 (DBV), -40 to 85 degC, Green (RoHS & no Sb/Br)"
U21: "SIMPLE SWITCHER Buck-Boost Converter For Negative Output Voltage in uSMD, YFX0008ADAC"
U22: "Single Output LDO, 200 mA, Adjustable -10 to -1.2 V Output, -10 to -2.7 V Input, 5-pin SOT-23 (DBV), -40 to 125 degC, Green (RoHS & no Sb/Br)"
USB: "MINI USB 2.0 SMT TYPE AB 5 CONTACTS R/A, SMD"
uWIRE: "Connector, 100mil Shrouded, 5x2, High-Temperature, Gold, TH"
VIN+ VIN-: "Connector, TH, SMA"
Y1: "OSC 100.0000MHZ 3.3V +-25PPM SMD"
Y2: "Crystal, 12Mhz, 18pF, SMD"
ZZ1: library part AssemblyNoteLabel
ZZ2 ZZ3 ZZ4: library part AssemblyNote

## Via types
v1: diameter 18, hole 8, Top Layer - L1 to Bottom Layer - L10, tented both sides, 1120 vias
v2: diameter 19.68, hole 7.87, Top Layer - L1 to Bottom Layer - L10, 99 vias
v3: diameter 18, hole 8, Top Layer - L1 to Bottom Layer - L10, tented bottom, 42 vias
v4: diameter 18, hole 8, Top Layer - L1 to Bottom Layer - L10, tented top, 36 vias
v5: diameter 25, hole 10, Top Layer - L1 to Bottom Layer - L10, tented both sides, 32 vias
v6: diameter 21.46, hole 10, Top Layer - L1 to Bottom Layer - L10, tented both sides, 26 vias
v7: diameter 18, hole 8.01, Top Layer - L1 to Bottom Layer - L10, tented both sides, 16 vias
v8: diameter 18, hole 8.01, Top Layer - L1 to Bottom Layer - L10, tented bottom, 16 vias
v9: diameter 25.98, hole 12.99, Top Layer - L1 to Bottom Layer - L10, tented top, 8 vias
v10: diameter 19.68, hole 7.87, Top Layer - L1 to Bottom Layer - L10, tented top, 5 vias
v11: diameter 126, hole 106, Top Layer - L1 to Bottom Layer - L10, tented top, 2 vias

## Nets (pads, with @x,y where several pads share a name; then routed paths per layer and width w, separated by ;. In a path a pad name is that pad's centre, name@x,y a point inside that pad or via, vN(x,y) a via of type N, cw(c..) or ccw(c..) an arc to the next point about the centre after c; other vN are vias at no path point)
1P8V_USB: 1P8USB.1 C133.1 C134.1 C136.1 C200.1 C212.2 U13.12 U13.37 U13.49 U13.64 | length 608
  Top Layer - L1 w10: v1(3124.5,419.1) U13.12@3178.97,419.1 ; v1(3233,760.97) 3249.83,744.14 U13.64@3249.83,706.5 ; U13.49@3545.11,706.5 3545.11,751.13 v1(3554.95,760.97) ; v1(3561.51,419.1) U13.37@3615.98,419.1 3658.83,419.1 C134.1@3670.44,407.49 3672.22,409.26 v1(3683,409.26)
  Top Layer - L1 w16.5: C133.1@3103.44,419.1 v1(3124.5,419.1) ; v1(3233,760.97) C136.1@3233,782.03
  Top Layer - L1 w24: v1(3554.95,760.97) 3554.95,785.96 C200.1@3558.7,789.7
  Bottom Layer - L10 w24: C212.2@3538,860.09 C212.2@3552.09,846 ; v1(3554.95,760.97) C212.2@3554.95,843.13 ; C212.2@3554.95,819 1P8USB.1@3687,819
